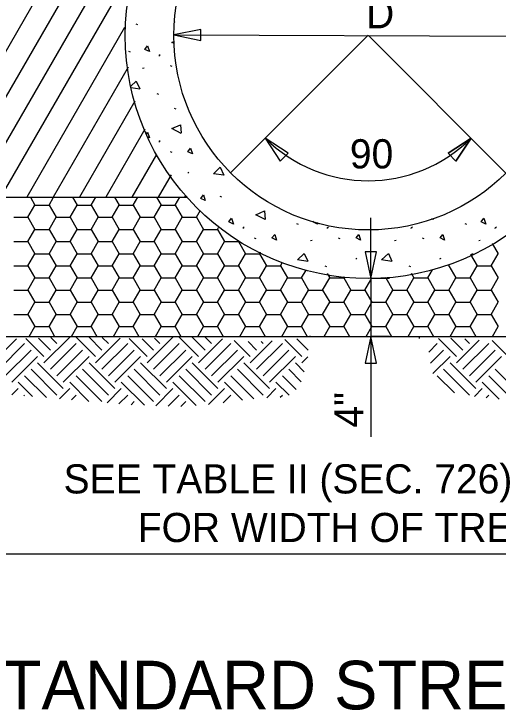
# Model space of a CAD drawing. Extents: x -439.1 to -407.9, y -458.1 to -436.2.
# Drawn here: x -423.375 to -420.885, y -446.951 to -443.37 of the extents above; entities that cross this region are included whole.
import ezdxf

# ---------------------------------------------------------------- set-up
doc = ezdxf.new("R2010")
doc.units = 0
doc.layers.add('Level 4', color=7, linetype='Continuous')
doc.layers.add('Level 45', color=7, linetype='Continuous')

msp = doc.modelspace()

# ---------------------------------------------------------------- linework, layer by layer
at = {"layer": 'Level 4'}
for p, q in [((-420.8581, -439.5989), (-423.5795, -444.3124)), ((-421.0426, -439.684), (-423.6394, -444.1818)), ((-421.1918, -439.708), (-423.6394, -443.9474)), ((-422.7493, -443.1089), (-423.4442, -444.3124)), ((-422.7374, -443.426), (-422.7457, -443.4223)), ((-422.546, -443.414), (-422.5483, -443.413)), ((-422.8055, -443.4406), (-423.3089, -444.3124)), ((-422.5521, -443.4785), (-420.5521, -443.4848)), ((-421.5534, -443.4803), (-422.2609, -444.1878)), ((-421.5534, -443.4806), (-421.5534, -443.4806)), ((-420.8447, -444.189), (-421.5522, -443.4815)), ((-421.5521, -443.4816), (-421.5521, -443.4816)), ((-422.7754, -443.5666), (-422.7837, -443.563)), ((-422.6301, -443.5859), (-422.6243, -443.5822)), ((-422.6275, -443.5822), (-422.6223, -443.5786)), ((-422.7875, -443.6437), (-423.1735, -444.3124)), ((-422.5613, -443.6406), (-422.5697, -443.6369)), ((-422.7139, -443.6489), (-422.7056, -443.6484)), ((-422.6301, -443.7848), (-422.6384, -443.7812)), ((-422.7535, -443.8192), (-423.0382, -444.3124)), ((-422.54, -443.8598), (-422.5483, -443.8562)), ((-422.7017, -443.9639), (-422.9029, -444.3124)), ((-422.6301, -444.0291), (-422.6243, -444.0255)), ((-422.6275, -444.0255), (-422.6223, -444.0218)), ((-422.641, -444.0932), (-422.7676, -444.3124)), ((-422.5613, -444.0838), (-422.5697, -444.0801)), ((-422.5665, -444.1985), (-422.6323, -444.3124)), ((-422.4806, -444.1874), (-422.4754, -444.1838)), ((-422.2606, -444.1877), (-422.2606, -444.1877)), ((-423.6397, -444.3128), (-422.4859, -444.3128)), ((-423.2903, -444.3124), (-423.2666, -444.3535)), ((-423.1944, -444.3535), (-423.1707, -444.3124)), ((-423.0738, -444.3124), (-423.0501, -444.3535)), ((-422.9779, -444.3535), (-422.9542, -444.3124)), ((-422.8573, -444.3124), (-422.8336, -444.3535)), ((-422.7614, -444.3535), (-422.7377, -444.3124)), ((-422.6408, -444.3124), (-422.617, -444.3535)), ((-422.5449, -444.3535), (-422.5212, -444.3124)), ((-422.4921, -444.3039), (-422.4969, -444.3124)), ((-422.3051, -444.3124), (-422.3134, -444.3088)), ((-423.3026, -444.416), (-423.2666, -444.3535)), ((-423.2666, -444.3535), (-423.1944, -444.3535)), ((-423.1944, -444.3535), (-423.1583, -444.416)), ((-423.0861, -444.416), (-423.0501, -444.3535)), ((-423.0501, -444.3535), (-422.9779, -444.3535)), ((-422.9779, -444.3535), (-422.9418, -444.416)), ((-422.8696, -444.416), (-422.8336, -444.3535)), ((-422.8336, -444.3535), (-422.7614, -444.3535)), ((-422.7614, -444.3535), (-422.7253, -444.416)), ((-422.6531, -444.416), (-422.617, -444.3535)), ((-422.617, -444.3535), (-422.5449, -444.3535)), ((-422.5449, -444.3535), (-422.5088, -444.416)), ((-422.4366, -444.416), (-422.4158, -444.3798)), ((-423.3748, -444.416), (-423.3026, -444.416)), ((-423.3026, -444.416), (-423.2666, -444.4785)), ((-423.1944, -444.4785), (-423.1583, -444.416)), ((-423.1583, -444.416), (-423.0861, -444.416)), ((-423.0861, -444.416), (-423.0501, -444.4785)), ((-422.9779, -444.4785), (-422.9418, -444.416)), ((-422.9418, -444.416), (-422.8696, -444.416)), ((-422.8696, -444.416), (-422.8336, -444.4785)), ((-422.7614, -444.4785), (-422.7253, -444.416)), ((-422.7253, -444.416), (-422.6531, -444.416)), ((-422.6531, -444.416), (-422.6171, -444.4785)), ((-422.5449, -444.4785), (-422.5088, -444.416)), ((-422.5088, -444.416), (-422.4366, -444.416)), ((-422.4366, -444.416), (-422.4005, -444.4785)), ((-421.5397, -444.7316), (-421.5397, -444.4191)), ((-422.3284, -444.4785), (-422.3229, -444.4689)), ((-422.1978, -444.4723), (-422.1921, -444.4687)), ((-422.1952, -444.4687), (-422.19, -444.465)), ((-421.9108, -444.4531), (-421.9191, -444.4494)), ((-421.7655, -444.4723), (-421.7598, -444.4687)), ((-421.7629, -444.4687), (-421.7577, -444.465)), ((-421.3332, -444.4723), (-421.3275, -444.4687)), ((-421.3306, -444.4687), (-421.3254, -444.465)), ((-421.0462, -444.4531), (-421.0546, -444.4494)), ((-420.9009, -444.4723), (-420.8952, -444.4687)), ((-420.8983, -444.4687), (-420.8931, -444.465)), ((-423.3026, -444.541), (-423.2666, -444.4785)), ((-423.2666, -444.4785), (-423.1944, -444.4785)), ((-423.1944, -444.4785), (-423.1583, -444.541)), ((-423.0861, -444.541), (-423.0501, -444.4785)), ((-423.0501, -444.4785), (-422.9779, -444.4785)), ((-422.9779, -444.4785), (-422.9418, -444.541)), ((-422.8696, -444.541), (-422.8336, -444.4785)), ((-422.8336, -444.4785), (-422.7614, -444.4785)), ((-422.7614, -444.4785), (-422.7253, -444.541)), ((-422.6531, -444.541), (-422.617, -444.4785)), ((-422.617, -444.4785), (-422.5449, -444.4785)), ((-422.5449, -444.4785), (-422.5088, -444.541)), ((-422.4366, -444.541), (-422.4005, -444.4785)), ((-422.4005, -444.4785), (-422.3284, -444.4785)), ((-422.3284, -444.4785), (-422.2923, -444.541)), ((-423.3748, -444.541), (-423.3026, -444.541)), ((-423.3026, -444.541), (-423.2666, -444.6035)), ((-423.1944, -444.6035), (-423.1583, -444.541)), ((-423.1583, -444.541), (-423.0861, -444.541)), ((-423.0861, -444.541), (-423.0501, -444.6035)), ((-422.9779, -444.6035), (-422.9418, -444.541)), ((-422.9418, -444.541), (-422.8696, -444.541)), ((-422.8696, -444.541), (-422.8336, -444.6035)), ((-422.7614, -444.6035), (-422.7253, -444.541)), ((-422.7253, -444.541), (-422.6531, -444.541)), ((-422.6531, -444.541), (-422.6171, -444.6035)), ((-422.5449, -444.6035), (-422.5088, -444.541)), ((-422.5088, -444.541), (-422.4366, -444.541)), ((-422.4366, -444.541), (-422.4005, -444.6035)), ((-422.3284, -444.6035), (-422.2923, -444.541)), ((-422.2923, -444.541), (-422.2201, -444.541)), ((-422.2201, -444.541), (-422.2176, -444.5367)), ((-422.2201, -444.541), (-422.184, -444.6035)), ((-422.129, -444.527), (-422.1374, -444.5234)), ((-421.8493, -444.5354), (-421.841, -444.5348)), ((-421.6967, -444.527), (-421.7051, -444.5234)), ((-421.4171, -444.5354), (-421.4087, -444.5348)), ((-421.2644, -444.527), (-421.2728, -444.5234)), ((-420.9848, -444.5354), (-420.9764, -444.5348)), ((-420.9151, -444.5512), (-420.885, -444.6035)), ((-423.3026, -444.666), (-423.2666, -444.6035)), ((-423.2666, -444.6035), (-423.1944, -444.6035)), ((-423.1944, -444.6035), (-423.1583, -444.666)), ((-423.0861, -444.666), (-423.0501, -444.6035)), ((-423.0501, -444.6035), (-422.9779, -444.6035)), ((-422.9779, -444.6035), (-422.9418, -444.666)), ((-422.8696, -444.666), (-422.8336, -444.6035)), ((-422.8336, -444.6035), (-422.7614, -444.6035)), ((-422.7614, -444.6035), (-422.7253, -444.666)), ((-422.6531, -444.666), (-422.617, -444.6035)), ((-422.617, -444.6035), (-422.5449, -444.6035)), ((-422.5449, -444.6035), (-422.5088, -444.666)), ((-422.4366, -444.666), (-422.4005, -444.6035)), ((-422.4005, -444.6035), (-422.3284, -444.6035)), ((-422.3284, -444.6035), (-422.2923, -444.666)), ((-422.2201, -444.666), (-422.184, -444.6035)), ((-422.184, -444.6035), (-422.1119, -444.6035)), ((-422.1119, -444.6035), (-422.1061, -444.5935)), ((-422.1119, -444.6035), (-422.0758, -444.666)), ((-421.0267, -444.6081), (-420.9932, -444.666)), ((-420.9211, -444.666), (-420.885, -444.6035)), ((-421.616, -444.6307), (-421.6108, -444.627)), ((-421.1837, -444.6307), (-421.1785, -444.627)), ((-423.3748, -444.666), (-423.3026, -444.666)), ((-423.3026, -444.666), (-423.2666, -444.7285)), ((-423.1944, -444.7285), (-423.1583, -444.666)), ((-423.1583, -444.666), (-423.0861, -444.666)), ((-423.0861, -444.666), (-423.0501, -444.7285)), ((-422.9779, -444.7285), (-422.9418, -444.666)), ((-422.9418, -444.666), (-422.8696, -444.666)), ((-422.8696, -444.666), (-422.8336, -444.7285)), ((-422.7614, -444.7285), (-422.7253, -444.666)), ((-422.7253, -444.666), (-422.6531, -444.666)), ((-422.6531, -444.666), (-422.6171, -444.7285)), ((-422.5449, -444.7285), (-422.5088, -444.666)), ((-422.5088, -444.666), (-422.4366, -444.666)), ((-422.4366, -444.666), (-422.4005, -444.7285)), ((-422.3284, -444.7285), (-422.2923, -444.666)), ((-422.2923, -444.666), (-422.2201, -444.666)), ((-422.2201, -444.666), (-422.184, -444.7285)), ((-422.1119, -444.7285), (-422.0758, -444.666)), ((-422.0758, -444.666), (-422.0036, -444.666)), ((-422.0036, -444.666), (-421.9946, -444.6503)), ((-422.0036, -444.666), (-421.9675, -444.7285)), ((-421.7655, -444.6713), (-421.7738, -444.6676)), ((-421.3332, -444.6713), (-421.3415, -444.6676)), ((-421.1403, -444.666), (-421.1376, -444.666)), ((-421.1376, -444.666), (-421.1364, -444.664)), ((-421.1376, -444.666), (-421.1015, -444.7285)), ((-421.0293, -444.7285), (-420.9932, -444.666)), ((-420.9932, -444.666), (-420.9211, -444.666)), ((-420.9211, -444.666), (-420.885, -444.7285)), ((-421.8954, -444.7285), (-421.8723, -444.6886)), ((-421.7641, -444.7057), (-421.751, -444.7285)), ((-421.6789, -444.7285), (-421.674, -444.72)), ((-421.3319, -444.7044), (-421.318, -444.7285)), ((-421.2458, -444.7285), (-421.2219, -444.687)), ((-423.3026, -444.791), (-423.2666, -444.7285)), ((-423.2666, -444.7285), (-423.1944, -444.7285)), ((-423.1944, -444.7285), (-423.1583, -444.791)), ((-423.0861, -444.791), (-423.0501, -444.7285)), ((-423.0501, -444.7285), (-422.9779, -444.7285)), ((-422.9779, -444.7285), (-422.9418, -444.791)), ((-422.8696, -444.791), (-422.8336, -444.7285)), ((-422.8336, -444.7285), (-422.7614, -444.7285)), ((-422.7614, -444.7285), (-422.7253, -444.791)), ((-422.6531, -444.791), (-422.617, -444.7285)), ((-422.617, -444.7285), (-422.5449, -444.7285)), ((-422.5449, -444.7285), (-422.5088, -444.791)), ((-422.4366, -444.791), (-422.4005, -444.7285)), ((-422.4005, -444.7285), (-422.3284, -444.7285)), ((-422.3284, -444.7285), (-422.2923, -444.791)), ((-422.2201, -444.791), (-422.184, -444.7285)), ((-422.184, -444.7285), (-422.1119, -444.7285)), ((-422.1119, -444.7285), (-422.0758, -444.791)), ((-422.0036, -444.791), (-421.9675, -444.7285)), ((-421.9675, -444.7285), (-421.8954, -444.7285)), ((-421.8954, -444.7285), (-421.8593, -444.791)), ((-421.7871, -444.791), (-421.751, -444.7285)), ((-421.751, -444.7285), (-421.6789, -444.7285)), ((-421.6789, -444.7285), (-421.6428, -444.791)), ((-421.5706, -444.791), (-421.5396, -444.7374)), ((-421.5397, -444.7316), (-421.5397, -445.0289)), ((-421.4427, -444.7316), (-421.5397, -444.7316)), ((-421.4836, -444.7285), (-421.4623, -444.7285)), ((-421.4623, -444.7285), (-421.4602, -444.7248)), ((-421.4623, -444.7285), (-421.4263, -444.791)), ((-421.3541, -444.791), (-421.318, -444.7285)), ((-421.318, -444.7285), (-421.2458, -444.7285)), ((-421.2458, -444.7285), (-421.2097, -444.791)), ((-421.1376, -444.791), (-421.1015, -444.7285)), ((-421.1015, -444.7285), (-421.0293, -444.7285)), ((-421.0293, -444.7285), (-420.9932, -444.791)), ((-420.9211, -444.791), (-420.885, -444.7285)), ((-423.3748, -444.791), (-423.3026, -444.791)), ((-423.3026, -444.791), (-423.2666, -444.8535)), ((-423.1944, -444.8535), (-423.1583, -444.791)), ((-423.1583, -444.791), (-423.0861, -444.791)), ((-423.0861, -444.791), (-423.0501, -444.8535)), ((-422.9779, -444.8535), (-422.9418, -444.791)), ((-422.9418, -444.791), (-422.8696, -444.791)), ((-422.8696, -444.791), (-422.8336, -444.8535)), ((-422.7614, -444.8535), (-422.7253, -444.791)), ((-422.7253, -444.791), (-422.6531, -444.791)), ((-422.6531, -444.791), (-422.617, -444.8535)), ((-422.5449, -444.8535), (-422.5088, -444.791)), ((-422.5088, -444.791), (-422.4366, -444.791)), ((-422.4366, -444.791), (-422.4005, -444.8535)), ((-422.3284, -444.8535), (-422.2923, -444.791)), ((-422.2923, -444.791), (-422.2201, -444.791)), ((-422.2201, -444.791), (-422.184, -444.8535)), ((-422.1119, -444.8535), (-422.0758, -444.791)), ((-422.0758, -444.791), (-422.0036, -444.791)), ((-422.0036, -444.791), (-421.9675, -444.8535)), ((-421.8954, -444.8535), (-421.8593, -444.791)), ((-421.8593, -444.791), (-421.7871, -444.791)), ((-421.7871, -444.791), (-421.751, -444.8535)), ((-421.6789, -444.8535), (-421.6428, -444.791)), ((-421.6428, -444.791), (-421.5706, -444.791)), ((-421.5706, -444.791), (-421.5345, -444.8535)), ((-421.4623, -444.8535), (-421.4263, -444.791)), ((-421.4263, -444.791), (-421.3541, -444.791)), ((-421.3541, -444.791), (-421.318, -444.8535)), ((-421.2458, -444.8535), (-421.2097, -444.791)), ((-421.2097, -444.791), (-421.1376, -444.791)), ((-421.1376, -444.791), (-421.1015, -444.8535)), ((-421.0293, -444.8535), (-420.9932, -444.791)), ((-420.9932, -444.791), (-420.9211, -444.791)), ((-420.9211, -444.791), (-420.885, -444.8535)), ((-423.3026, -444.916), (-423.2666, -444.8535)), ((-423.2666, -444.8535), (-423.1944, -444.8535)), ((-423.1944, -444.8535), (-423.1583, -444.916)), ((-423.0861, -444.916), (-423.0501, -444.8535)), ((-423.0501, -444.8535), (-422.9779, -444.8535)), ((-422.9779, -444.8535), (-422.9418, -444.916)), ((-422.8696, -444.916), (-422.8336, -444.8535)), ((-422.8336, -444.8535), (-422.7614, -444.8535)), ((-422.7614, -444.8535), (-422.7253, -444.916)), ((-422.6531, -444.916), (-422.617, -444.8535)), ((-422.617, -444.8535), (-422.5449, -444.8535)), ((-422.5449, -444.8535), (-422.5088, -444.916)), ((-422.4366, -444.916), (-422.4005, -444.8535)), ((-422.4005, -444.8535), (-422.3284, -444.8535)), ((-422.3284, -444.8535), (-422.2923, -444.916)), ((-422.2201, -444.916), (-422.184, -444.8535)), ((-422.184, -444.8535), (-422.1119, -444.8535)), ((-422.1119, -444.8535), (-422.0758, -444.916)), ((-422.0036, -444.916), (-421.9675, -444.8535)), ((-421.9675, -444.8535), (-421.8954, -444.8535)), ((-421.8954, -444.8535), (-421.8593, -444.916)), ((-421.7871, -444.916), (-421.751, -444.8535)), ((-421.751, -444.8535), (-421.6789, -444.8535)), ((-421.6789, -444.8535), (-421.6428, -444.916)), ((-421.5706, -444.916), (-421.5345, -444.8535)), ((-421.5345, -444.8535), (-421.4623, -444.8535)), ((-421.4623, -444.8535), (-421.4263, -444.916)), ((-421.3541, -444.916), (-421.318, -444.8535)), ((-421.318, -444.8535), (-421.2458, -444.8535)), ((-421.2458, -444.8535), (-421.2098, -444.916)), ((-421.1376, -444.916), (-421.1015, -444.8535)), ((-421.1015, -444.8535), (-421.0293, -444.8535)), ((-421.0293, -444.8535), (-420.9932, -444.916)), ((-420.9211, -444.916), (-420.885, -444.8535)), ((-423.3748, -444.916), (-423.3026, -444.916)), ((-423.3026, -444.916), (-423.2666, -444.9785)), ((-423.1944, -444.9785), (-423.1583, -444.916)), ((-423.1583, -444.916), (-423.0861, -444.916)), ((-423.0861, -444.916), (-423.0501, -444.9785)), ((-422.9779, -444.9785), (-422.9418, -444.916)), ((-422.9418, -444.916), (-422.8696, -444.916)), ((-422.8696, -444.916), (-422.8336, -444.9785)), ((-422.7614, -444.9785), (-422.7253, -444.916)), ((-422.7253, -444.916), (-422.6531, -444.916)), ((-422.6531, -444.916), (-422.617, -444.9785)), ((-422.5449, -444.9785), (-422.5088, -444.916)), ((-422.5088, -444.916), (-422.4366, -444.916)), ((-422.4366, -444.916), (-422.4005, -444.9785)), ((-422.3284, -444.9785), (-422.2923, -444.916)), ((-422.2923, -444.916), (-422.2201, -444.916)), ((-422.2201, -444.916), (-422.184, -444.9785)), ((-422.1119, -444.9785), (-422.0758, -444.916)), ((-422.0758, -444.916), (-422.0036, -444.916)), ((-422.0036, -444.916), (-421.9675, -444.9785)), ((-421.8954, -444.9785), (-421.8593, -444.916)), ((-421.8593, -444.916), (-421.7871, -444.916)), ((-421.7871, -444.916), (-421.751, -444.9785)), ((-421.6789, -444.9785), (-421.6428, -444.916)), ((-421.6428, -444.916), (-421.5706, -444.916)), ((-421.5706, -444.916), (-421.5345, -444.9785)), ((-421.4623, -444.9785), (-421.4263, -444.916)), ((-421.4263, -444.916), (-421.3541, -444.916)), ((-421.3541, -444.916), (-421.318, -444.9785)), ((-421.2458, -444.9785), (-421.2097, -444.916)), ((-421.2097, -444.916), (-421.1376, -444.916)), ((-421.1376, -444.916), (-421.1015, -444.9785)), ((-421.0293, -444.9785), (-420.9932, -444.916)), ((-420.9932, -444.916), (-420.9211, -444.916)), ((-420.9211, -444.916), (-420.885, -444.9785)), ((-423.2957, -445.0289), (-423.2666, -444.9785)), ((-423.2666, -444.9785), (-423.1944, -444.9785)), ((-423.1944, -444.9785), (-423.1653, -445.0289)), ((-423.0792, -445.0289), (-423.0501, -444.9785)), ((-423.0501, -444.9785), (-422.9779, -444.9785)), ((-422.9779, -444.9785), (-422.9488, -445.0289)), ((-422.8627, -445.0289), (-422.8336, -444.9785)), ((-422.8336, -444.9785), (-422.7614, -444.9785)), ((-422.7614, -444.9785), (-422.7323, -445.0289)), ((-422.6462, -445.0289), (-422.617, -444.9785)), ((-422.617, -444.9785), (-422.5449, -444.9785)), ((-422.5449, -444.9785), (-422.5157, -445.0289)), ((-422.4297, -445.0289), (-422.4005, -444.9785)), ((-422.4005, -444.9785), (-422.3284, -444.9785)), ((-422.3284, -444.9785), (-422.2992, -445.0289)), ((-422.2132, -445.0289), (-422.184, -444.9785)), ((-422.184, -444.9785), (-422.1119, -444.9785)), ((-422.1119, -444.9785), (-422.0827, -445.0289)), ((-421.9967, -445.0289), (-421.9675, -444.9785)), ((-421.9675, -444.9785), (-421.8954, -444.9785)), ((-421.8954, -444.9785), (-421.8662, -445.0289)), ((-421.7801, -445.0289), (-421.751, -444.9785)), ((-421.751, -444.9785), (-421.6789, -444.9785)), ((-421.6789, -444.9785), (-421.6497, -445.0289)), ((-421.5636, -445.0289), (-421.5345, -444.9785)), ((-421.5345, -444.9785), (-421.4623, -444.9785)), ((-421.4623, -444.9785), (-421.4332, -445.0289)), ((-421.3471, -445.0289), (-421.318, -444.9785)), ((-421.318, -444.9785), (-421.2458, -444.9785)), ((-421.2458, -444.9785), (-421.2167, -445.0289)), ((-421.1306, -445.0289), (-421.1015, -444.9785)), ((-421.1015, -444.9785), (-421.0293, -444.9785)), ((-421.0293, -444.9785), (-421.0002, -445.0289)), ((-420.9141, -445.0289), (-420.885, -444.9785)), ((-423.6397, -445.029), (-419.4859, -445.029)), ((-423.4855, -445.1652), (-423.3612, -445.0409)), ((-423.2203, -445.132), (-423.3129, -445.0394)), ((-423.1871, -445.0989), (-423.2487, -445.0373)), ((-423.2203, -445.1652), (-423.0877, -445.0326)), ((-423.154, -445.0657), (-423.1845, -445.0352)), ((-422.9551, -445.132), (-423.0561, -445.0311)), ((-422.922, -445.0989), (-422.9892, -445.0316)), ((-422.9551, -445.1652), (-422.8278, -445.0378)), ((-422.8888, -445.0657), (-422.9203, -445.0343)), ((-422.69, -445.132), (-422.7824, -445.0396)), ((-422.6568, -445.0989), (-422.7151, -445.0406)), ((-422.69, -445.1652), (-422.5574, -445.0326)), ((-422.6237, -445.0657), (-422.6514, -445.038)), ((-422.4248, -445.132), (-422.5259, -445.0309)), ((-422.3917, -445.0989), (-422.4611, -445.0295)), ((-422.4248, -445.1652), (-422.3018, -445.0421)), ((-422.3585, -445.0657), (-422.3924, -445.0319)), ((-421.8613, -445.0989), (-421.9195, -445.0407)), ((-421.8522, -445.029), (-421.8522, -445.0265)), ((-421.5397, -445.0289), (-421.5397, -445.3414)), ((-421.4427, -445.0289), (-421.5397, -445.0289)), ((-421.5397, -445.0289), (-421.5397, -445.5462)), ((-421.2897, -445.039), (-421.2897, -445.029)), ((-421.099, -445.132), (-421.1915, -445.0395)), ((-421.0658, -445.0989), (-421.1272, -445.0375)), ((-421.0327, -445.0657), (-421.0563, -445.0421)), ((-423.4523, -445.1983), (-423.3197, -445.0657)), ((-423.1871, -445.1983), (-423.0546, -445.0657)), ((-422.922, -445.1983), (-422.7894, -445.0657)), ((-422.6568, -445.1983), (-422.5242, -445.0657)), ((-422.3917, -445.1983), (-422.2591, -445.0657)), ((-422.1596, -445.132), (-422.2414, -445.0503)), ((-422.1265, -445.0989), (-422.1695, -445.0558)), ((-422.1596, -445.1652), (-422.0469, -445.0525)), ((-422.1265, -445.1983), (-421.9939, -445.0657)), ((-422.0933, -445.0657), (-422.104, -445.055)), ((-421.8945, -445.132), (-421.9823, -445.0441)), ((-421.2419, -445.1092), (-421.1984, -445.0657)), ((-421.099, -445.1652), (-420.982, -445.0482)), ((-421.0658, -445.1983), (-420.9332, -445.0657)), ((-420.8338, -445.132), (-420.9153, -445.0505)), ((-423.4192, -445.2314), (-423.2866, -445.0989)), ((-423.154, -445.2314), (-423.0214, -445.0989)), ((-422.8888, -445.2314), (-422.7562, -445.0989)), ((-422.6237, -445.2314), (-422.4911, -445.0989)), ((-422.3585, -445.2314), (-422.2259, -445.0989)), ((-422.0933, -445.2314), (-421.9608, -445.0989)), ((-421.2327, -445.1663), (-421.1653, -445.0989)), ((-421.0327, -445.2314), (-420.9001, -445.0989)), ((-423.386, -445.2646), (-423.2534, -445.132)), ((-423.1209, -445.2646), (-422.9883, -445.132)), ((-422.8557, -445.2646), (-422.7231, -445.132)), ((-422.5905, -445.2646), (-422.4579, -445.132)), ((-422.3254, -445.2646), (-422.1928, -445.132)), ((-422.0602, -445.2646), (-421.9276, -445.132)), ((-421.8945, -445.1652), (-421.8641, -445.1348)), ((-421.2201, -445.22), (-421.1321, -445.132)), ((-420.9995, -445.2646), (-420.867, -445.132)), ((-423.1209, -445.2977), (-423.2534, -445.1652)), ((-422.8557, -445.2977), (-422.9883, -445.1652)), ((-422.5905, -445.2977), (-422.7231, -445.1652)), ((-422.3254, -445.2977), (-422.4579, -445.1652)), ((-422.0602, -445.2977), (-422.1928, -445.1652)), ((-421.8815, -445.2113), (-421.9276, -445.1652)), ((-420.9995, -445.2977), (-421.1321, -445.1652)), ((-423.154, -445.3309), (-423.2866, -445.1983)), ((-422.8888, -445.3309), (-423.0214, -445.1983)), ((-422.6237, -445.3309), (-422.7562, -445.1983)), ((-422.3585, -445.3309), (-422.4911, -445.1983)), ((-422.0933, -445.3309), (-422.2259, -445.1983)), ((-421.8969, -445.2622), (-421.9608, -445.1983)), ((-421.0327, -445.3309), (-421.1653, -445.1983)), ((-420.7675, -445.3309), (-420.9001, -445.1983)), ((-423.2078, -445.3433), (-423.3197, -445.2314)), ((-422.922, -445.364), (-423.0546, -445.2314)), ((-422.6568, -445.364), (-422.7894, -445.2314)), ((-422.3917, -445.364), (-422.5242, -445.2314)), ((-422.1406, -445.3499), (-422.2591, -445.2314)), ((-421.9229, -445.3025), (-421.9939, -445.2314)), ((-421.1099, -445.32), (-421.1984, -445.2314)), ((-420.8038, -445.3609), (-420.9332, -445.2314)), ((-423.2799, -445.3376), (-423.3529, -445.2646)), ((-422.9889, -445.3634), (-423.0877, -445.2646)), ((-422.7041, -445.3831), (-422.8225, -445.2646)), ((-422.438, -445.3839), (-422.5574, -445.2646)), ((-422.1993, -445.3576), (-422.2922, -445.2646)), ((-421.96, -445.3316), (-422.0271, -445.2646)), ((-420.8795, -445.3515), (-420.9664, -445.2646)), ((-423.3849, -445.3298), (-423.3529, -445.2977)), ((-423.1396, -445.3496), (-423.0877, -445.2977)), ((-422.896, -445.3712), (-422.8225, -445.2977)), ((-422.6452, -445.3855), (-422.5574, -445.2977)), ((-422.3742, -445.3797), (-422.2922, -445.2977)), ((-422.0746, -445.3453), (-422.0271, -445.2977)), ((-421.0061, -445.3374), (-420.9664, -445.2977)), ((-423.3232, -445.3344), (-423.3197, -445.3309)), ((-423.0794, -445.3558), (-423.0546, -445.3309)), ((-422.8348, -445.3763), (-422.7894, -445.3309)), ((-422.7725, -445.3802), (-422.7562, -445.364)), ((-422.5815, -445.3882), (-422.5242, -445.3309)), ((-422.5162, -445.3892), (-422.4911, -445.364)), ((-422.2987, -445.3705), (-422.2591, -445.3309)), ((-422.0052, -445.3422), (-421.9939, -445.3309)), ((-420.9464, -445.3441), (-420.9332, -445.3309)), ((-419.4856, -446.1481), (-423.6394, -446.1481))]:
    msp.add_line(p, q, dxfattribs=at)
for points in [[(-422.4137, -443.4502), (-422.5521, -443.4785), (-422.4139, -443.5076)], [(-421.9643, -444.087), (-422.0824, -444.0095), (-422.0049, -444.1276)], [(-421.1423, -444.087), (-421.0242, -444.0095), (-421.1017, -444.1276)], [(-421.5684, -444.5933), (-421.5397, -444.7316), (-421.511, -444.5933)], [(-421.511, -445.1672), (-421.5397, -445.0289), (-421.5684, -445.1672)]]:
    msp.add_lwpolyline(points, close=True, dxfattribs=at)
for points in [[(-422.678, -443.5645), (-422.7014, -443.5536), (-422.6874, -443.5348), (-422.678, -443.5645)], [(-422.5496, -443.5233), (-422.5624, -443.5166), (-422.5492, -443.5106)], [(-422.773, -443.742), (-422.7462, -443.7161), (-422.728, -443.7557)], [(-422.728, -443.7567), (-422.7717, -443.7506)], [(-422.515, -443.9848), (-422.5624, -443.9598), (-422.5186, -443.94), (-422.515, -443.9838)], [(-422.6936, -443.9864), (-422.6874, -443.9781), (-422.678, -444.0077)], [(-422.678, -444.0077), (-422.6839, -444.005)], [(-421.9643, -444.087), (-422.0824, -444.0095), (-422.0049, -444.1276)], [(-421.1017, -444.1276), (-421.0242, -444.0095), (-421.1423, -444.087)], [(-422.4566, -444.09), (-422.4801, -444.0791), (-422.466, -444.0609), (-422.4566, -444.09)], [(-422.2957, -444.1999), (-422.3483, -444.1926), (-422.3139, -444.1593), (-422.2957, -444.1989)], [(-422.3905, -444.3307), (-422.4139, -444.3197), (-422.3999, -444.301), (-422.3905, -444.3307)], [(-422.0827, -444.4281), (-422.1301, -444.4031), (-422.0863, -444.3833), (-422.0827, -444.427)], [(-422.2457, -444.451), (-422.2691, -444.44), (-422.2551, -444.4213), (-422.2457, -444.451)], [(-421.2181, -444.4281), (-421.2261, -444.4238)], [(-421.2185, -444.4217), (-421.2181, -444.427)], [(-420.9488, -444.451), (-420.9723, -444.44), (-420.9582, -444.4213), (-420.9488, -444.451)], [(-421.8134, -444.451), (-421.8368, -444.44), (-421.8341, -444.4364)], [(-421.8164, -444.4416), (-421.8134, -444.451)], [(-422.0243, -444.5333), (-422.0478, -444.5223), (-422.0337, -444.5041), (-422.0243, -444.5333)], [(-421.5921, -444.5333), (-421.6155, -444.5223), (-421.6014, -444.5041), (-421.5921, -444.5333)], [(-421.1598, -444.5333), (-421.1832, -444.5223), (-421.1691, -444.5041), (-421.1598, -444.5333)], [(-421.8634, -444.6432), (-421.916, -444.6359), (-421.8816, -444.6025), (-421.8634, -444.6421)], [(-421.4311, -444.6432), (-421.4837, -444.6359), (-421.4493, -444.6025), (-421.4311, -444.6421)], [(-421.025, -444.6102), (-421.0171, -444.6025), (-421.0155, -444.6059)]]:
    msp.add_lwpolyline(points, dxfattribs=at)
for radius in [1.25, 1]:
    msp.add_circle((-421.5521, -443.4816), radius, dxfattribs=at)
msp.add_arc((-421.5533, -443.4804), 0.7482, 225, 315, dxfattribs=at)

# ---------------------------------------------------------------- texts
msp.add_text('D', height=0.15, rotation=359.8, dxfattribs=at).set_placement((-421.5642, -443.4441))
for s, height, p in [('90', 0.15, (-421.6472, -444.1648)), ('SEE TABLE II (SEC. 726) ', 0.15, (-423.1193, -445.8367)), ('FOR WIDTH OF TRENCH', 0.15, (-422.738, -446.0867)), ('STANDARD STRENGTH', 0.25, (-423.6602, -446.9472))]:
    msp.add_text(s, height=height, dxfattribs=at).set_placement(p)
at = {"layer": 'Level 45'}
msp.add_text('4"', height=0.15, rotation=90, dxfattribs=at).set_placement((-421.5772, -445.498))

doc.saveas('drawing.dxf')
